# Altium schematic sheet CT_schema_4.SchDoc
size 454 x 430 mm
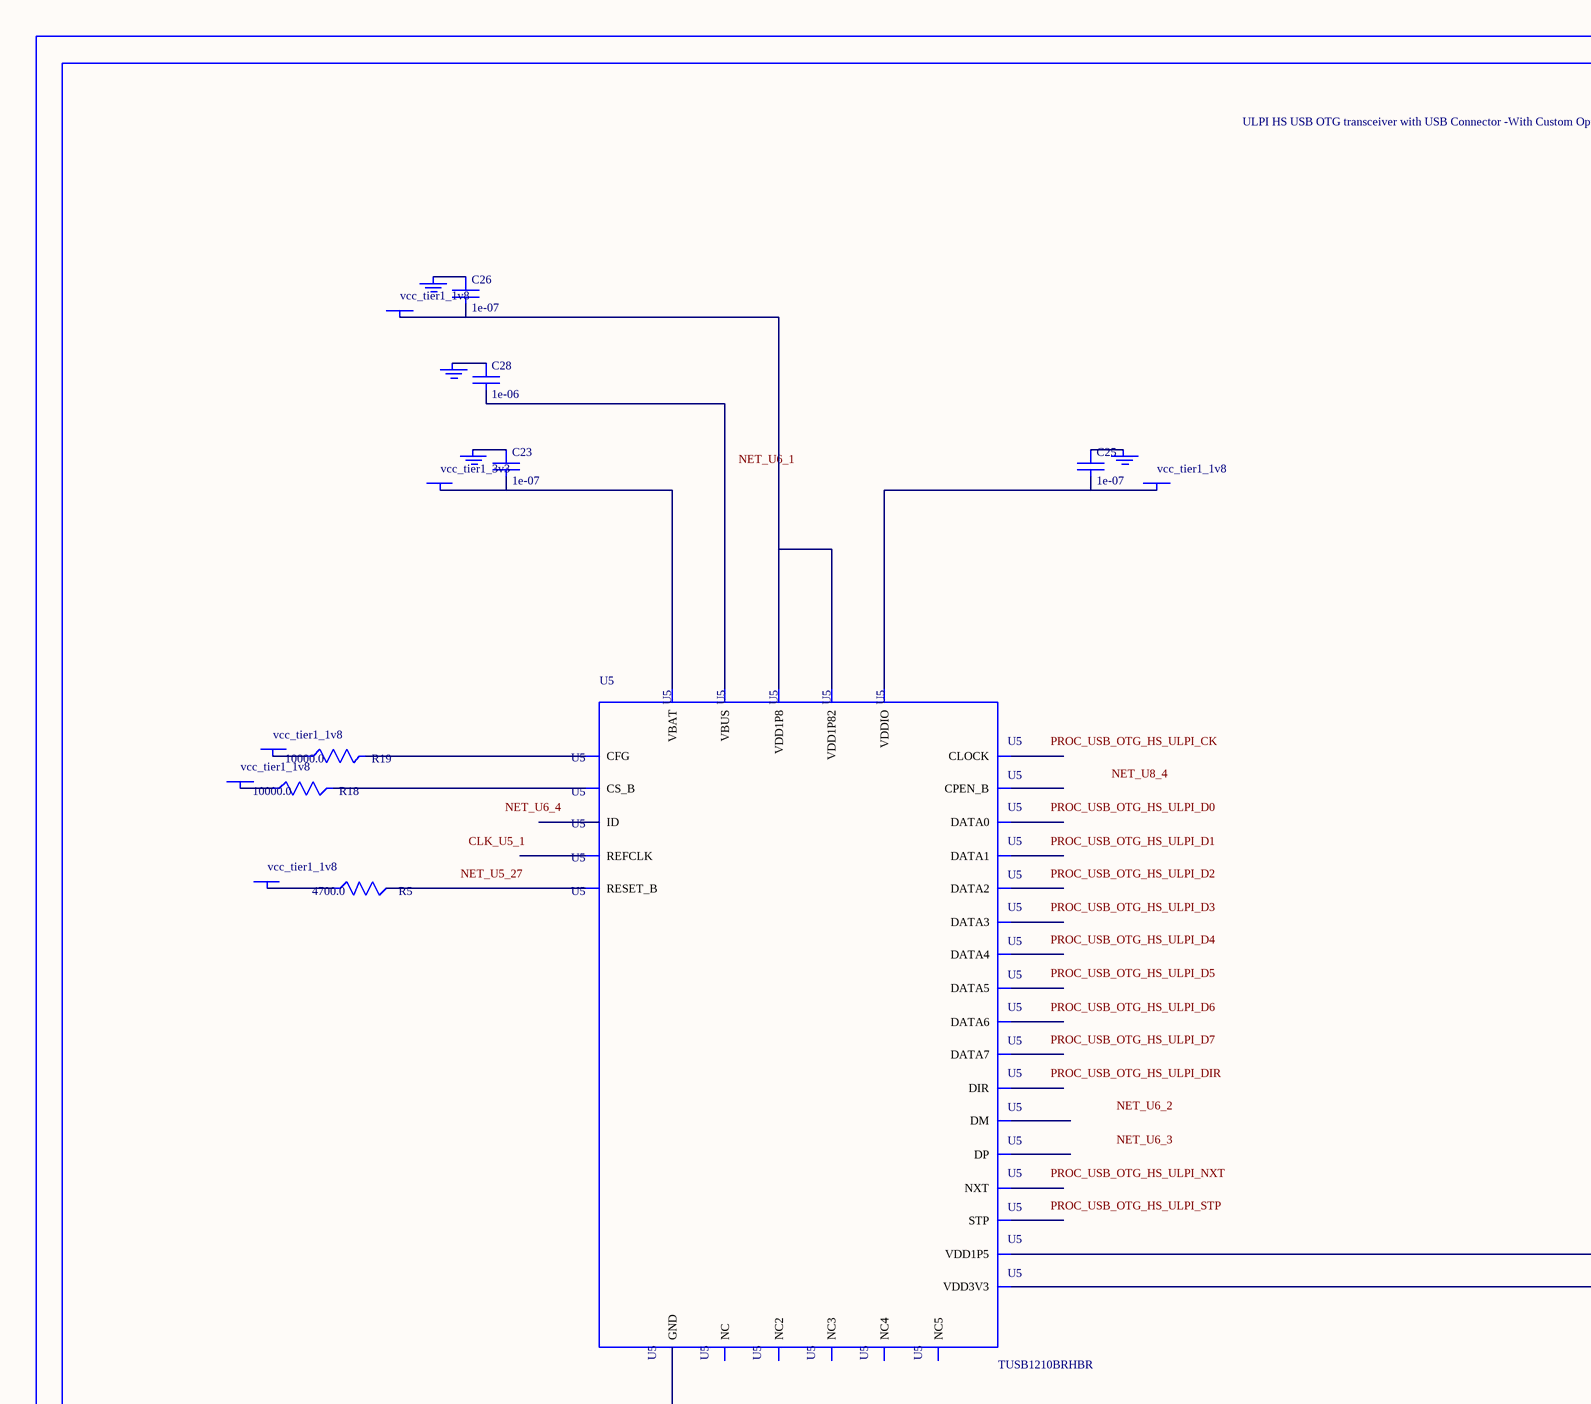
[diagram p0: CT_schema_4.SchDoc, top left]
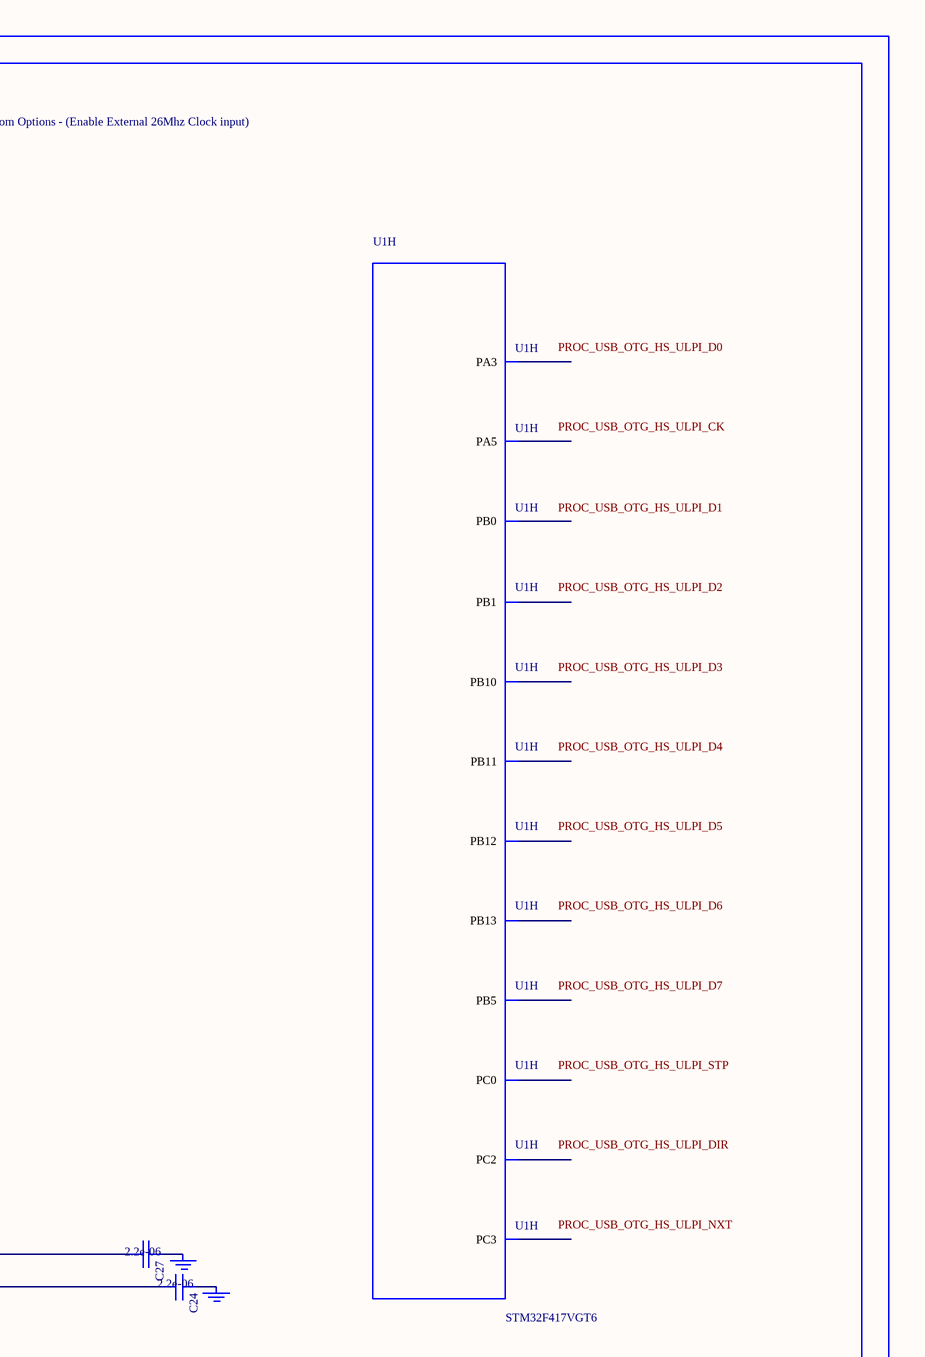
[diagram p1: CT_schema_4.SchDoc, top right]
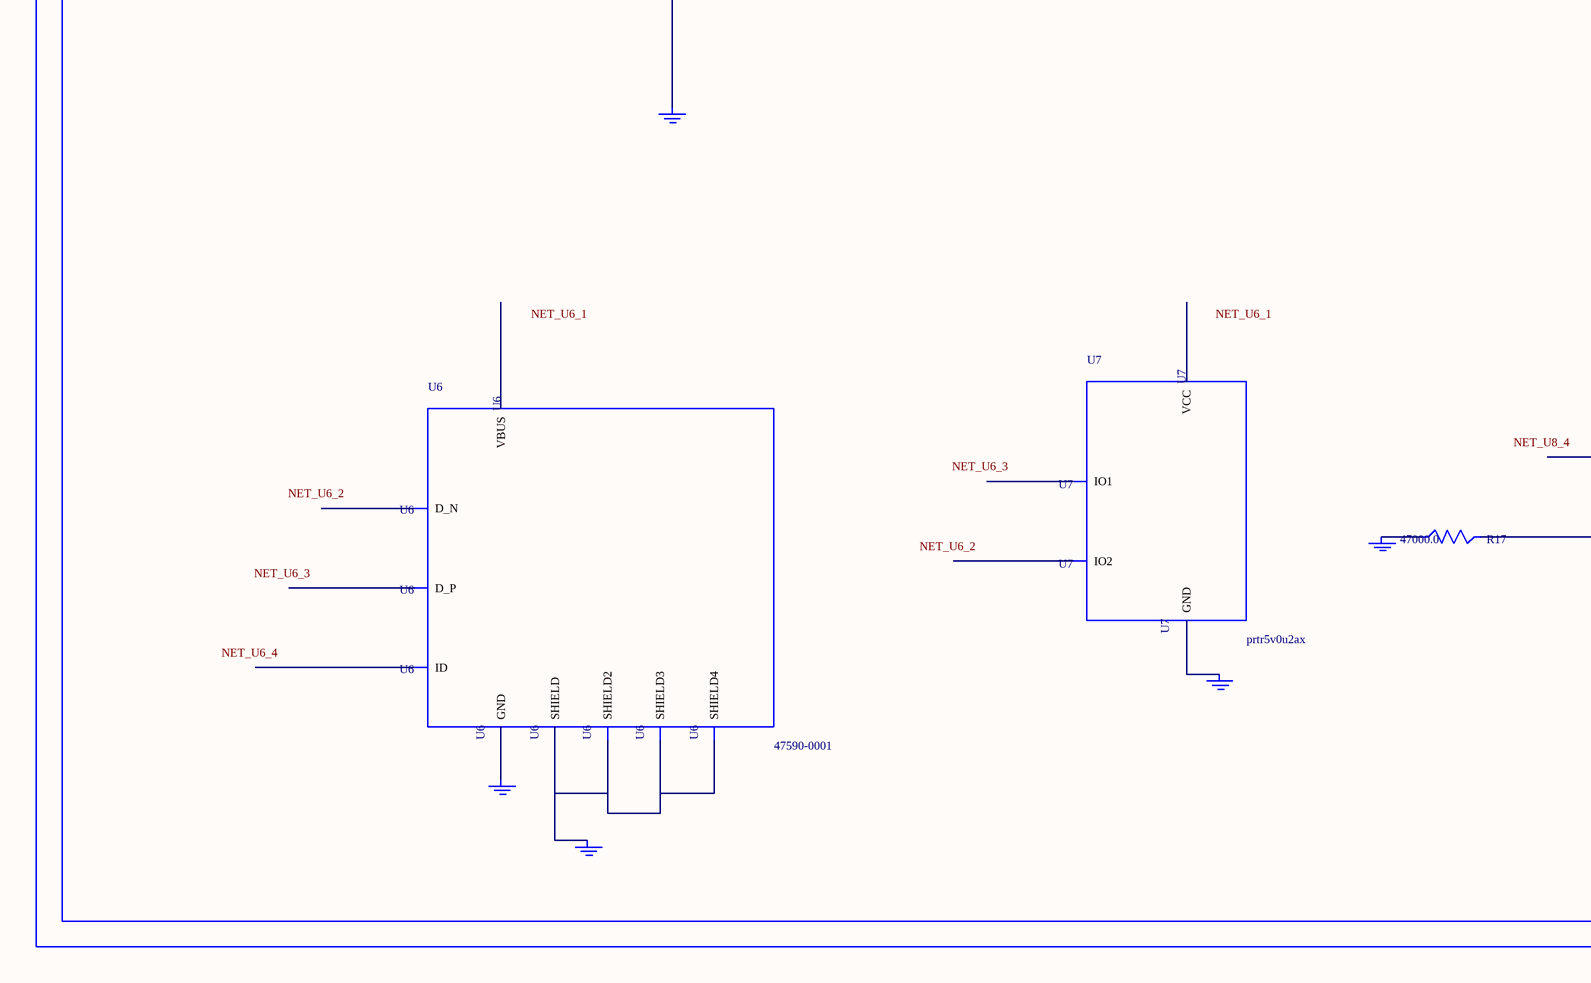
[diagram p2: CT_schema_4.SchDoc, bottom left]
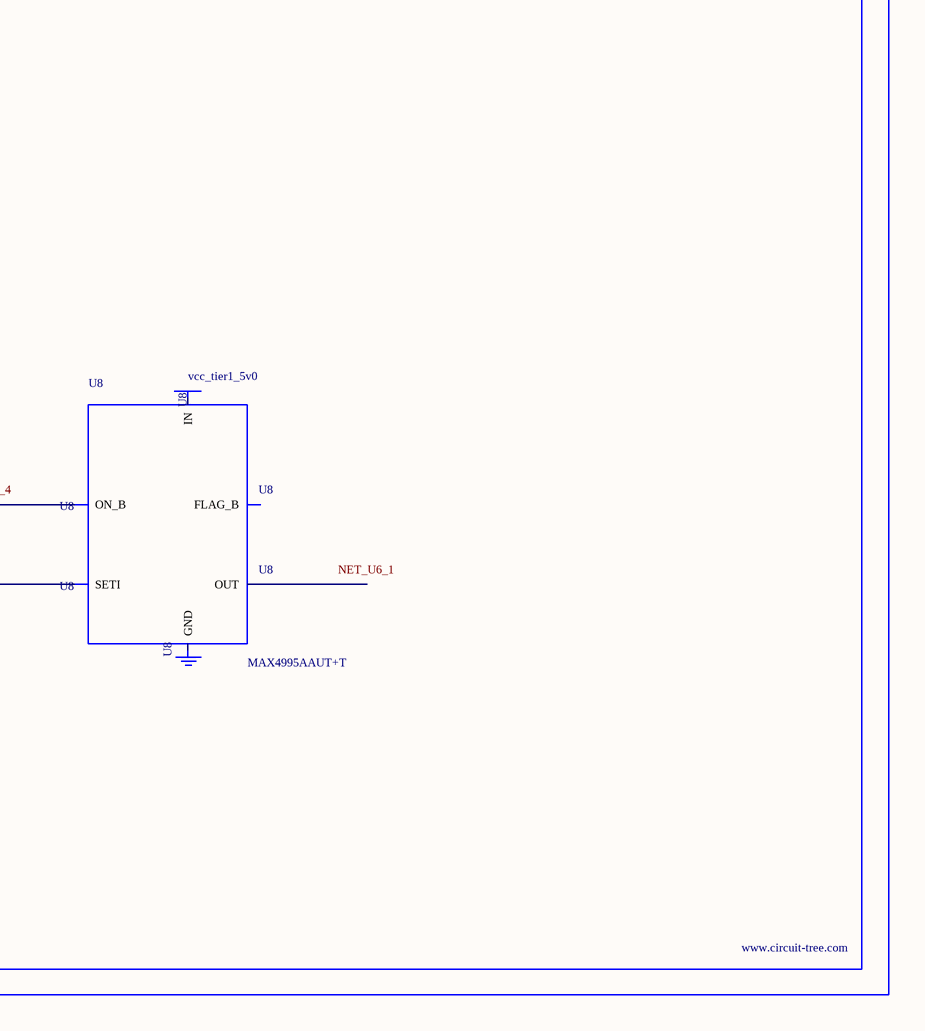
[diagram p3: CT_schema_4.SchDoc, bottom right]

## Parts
BORDER3  (no value)
C23  1e-07  [C0402]
C24  2.2e-06  [C0603]
C25  1e-07  [C0402]
C26  1e-07  [C0402]
C27  2.2e-06  [C0603]
C28  1e-06  [C0603]
GND_INSTANCE_3_0  (no value)
GND_INSTANCE_3_1  (no value)
GND_INSTANCE_3_2  (no value)
GND_INSTANCE_3_3  (no value)
GND_INSTANCE_3_4  (no value)
GND_INSTANCE_3_5  (no value)
GND_INSTANCE_3_6  (no value)
GND_INSTANCE_3_7  (no value)
GND_INSTANCE_3_8  (no value)
GND_INSTANCE_3_9  (no value)
GND_INSTANCE_3_10  (no value)
GND_INSTANCE_3_11  (no value)
POWER_INSTANCE_3_0  vcc_tier1_1v8
POWER_INSTANCE_3_1  vcc_tier1_1v8
POWER_INSTANCE_3_2  vcc_tier1_3v3
POWER_INSTANCE_3_3  vcc_tier1_1v8
POWER_INSTANCE_3_4  vcc_tier1_1v8
POWER_INSTANCE_3_5  vcc_tier1_1v8
POWER_INSTANCE_3_6  vcc_tier1_5v0
R5  4700.0  [R0603]
R17  47000.0  [R0603]
R18  10000.0  [R0603]
R19  10000.0  [R0603]
U1  STM32F417VGT6  [LQFP100]  (part H of 8)
U5  TUSB1210BRHBR  [RHB32_3P45X3P45]
U6  47590-0001  [MICRO_USB_AB]
U7  prtr5v0u2ax  [SOT143B]
U8  MAX4995AAUT+T  [SOT-23-6]

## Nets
NetC23_1: C23.1 GND_INSTANCE_3_2.0(GND)
NetC23_2: C23.2 POWER_INSTANCE_3_2.0(PWR) U5.21(VBAT)
NetC24_1: C24.1 GND_INSTANCE_3_1.0(GND)
NetC24_2: C24.2 U5.20(VDD3V3)
NetC25_1: C25.1 GND_INSTANCE_3_5.0(GND)
NetC25_2: C25.2 POWER_INSTANCE_3_4.0(PWR) U5.32(VDDIO)
NetC26_1: C26.1 GND_INSTANCE_3_4.0(GND)
NetC26_2: C26.2 POWER_INSTANCE_3_3.0(PWR) U5.28(VDD1P8) U5.30(VDD1P82)
NetC27_1: C27.1 GND_INSTANCE_3_0.0(GND)
NetC27_2: C27.2 U5.12(VDD1P5)
NetC28_1: C28.1 GND_INSTANCE_3_3.0(GND)
NetC28_2: C28.2 U5.22(VBUS)
NetGND_INSTANCE_3_6_0: GND_INSTANCE_3_6.0(GND) U5.33(GND)
NetGND_INSTANCE_3_7_0: GND_INSTANCE_3_7.0(GND) U6.6(SHIELD) U6.7(SHIELD2) U6.8(SHIELD3) U6.9(SHIELD4)
NetGND_INSTANCE_3_8_0: GND_INSTANCE_3_8.0(GND) U6.5(GND)
NetGND_INSTANCE_3_9_0: GND_INSTANCE_3_9.0(GND) U7.1(GND)
NetGND_INSTANCE_3_10_0: GND_INSTANCE_3_10.0(GND) R17.1
NetPOWER_INSTANCE_3_0_0: POWER_INSTANCE_3_0.0(PWR) R18.1
NetPOWER_INSTANCE_3_1_0: POWER_INSTANCE_3_1.0(PWR) R19.1
NetPOWER_INSTANCE_3_5_0: POWER_INSTANCE_3_5.0(PWR) R5.1
NetR5_2: R5.2 U5.27(RESET_B)
NetR17_2: R17.2 U8.3(SETI)
NetR18_2: R18.2 U5.11(CS_B)
NetR19_2: R19.2 U5.14(CFG)

Not connected (* = marked no-connect by the designer): GND_INSTANCE_3_11 0(GND); POWER_INSTANCE_3_6 0(PWR); U1 15(PC0) 17(PC2) 18(PC3) 26(PA3) 30(PA5) 35(PB0) 36(PB1) 47(PB10) 48(PB11) 51(PB12) 52(PB13) 91(PB5); U5 1(REFCLK) 2(NXT) 3(DATA0) 4(DATA1) 5(DATA2) 6(DATA3) 7(DATA4) 8(NC) 9(DATA5) 10(DATA6) 13(DATA7) 15(NC2) 16(NC3) 17(CPEN_B) 18(DP) 19(DM) 23(ID) 24(NC4) 25(NC5) 26(CLOCK) 29(STP) 31(DIR); U6 1(VBUS) 2(D_N) 3(D_P) 4(ID); U7 2(IO1) 3(IO2) 4(VCC); U8 1(OUT) 2(GND) 4(ON_B) 5(IN) 6(FLAG_B)

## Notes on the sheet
- Labels drawn without touching a wire or pin: CLK_U5_1, NET_U5_27, NET_U6_1, NET_U6_2, NET_U6_3, NET_U6_4, NET_U8_4, PROC_USB_OTG_HS_ULPI_CK, PROC_USB_OTG_HS_ULPI_D0, PROC_USB_OTG_HS_ULPI_D1, PROC_USB_OTG_HS_ULPI_D2, PROC_USB_OTG_HS_ULPI_D3, PROC_USB_OTG_HS_ULPI_D4, PROC_USB_OTG_HS_ULPI_D5, PROC_USB_OTG_HS_ULPI_D6, PROC_USB_OTG_HS_ULPI_D7, PROC_USB_OTG_HS_ULPI_DIR, PROC_USB_OTG_HS_ULPI_NXT, PROC_USB_OTG_HS_ULPI_STP

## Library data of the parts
BORDER3 = BORDER_PAGE3
C23 C25 C26 = C0402C104K3RACTU
C24 C27 = C0603C225K8RACTU
C28 = C0603C105K3RACTU
GND_INSTANCE_3_0-GND_INSTANCE_3_11 = GND
POWER_INSTANCE_3_0-POWER_INSTANCE_3_6 = PWR
R5 = RC0603JR-074K7L
R17 = RC0603JR-0747KL
R18 R19 = RC0603JR-0710KL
